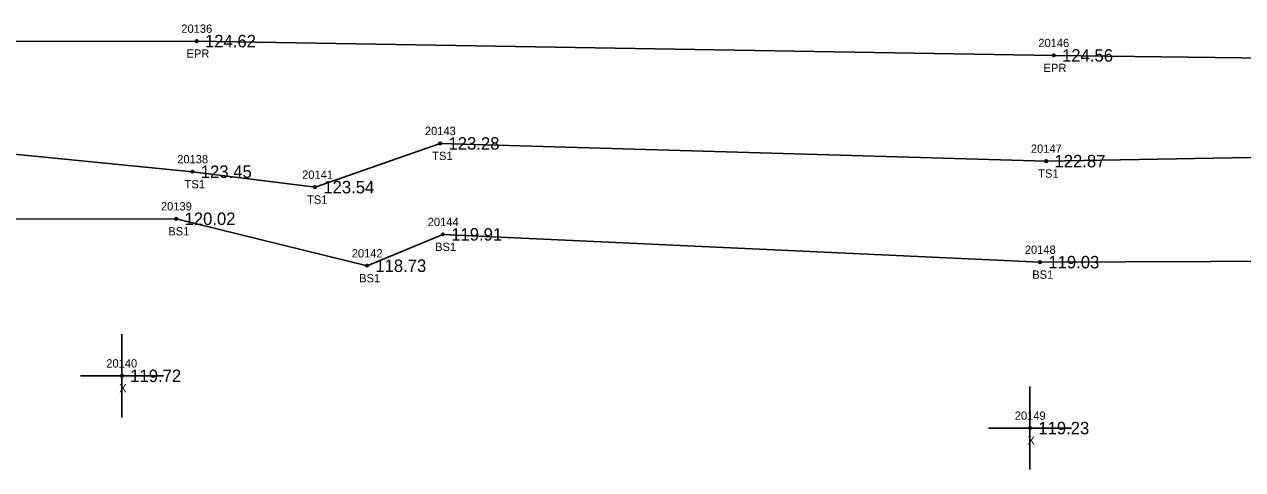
# Model space of a CAD drawing. Extents: x 2375812 to 2377225, y 1024470 to 1025135.
# Drawn here: x 2376638 to 2376784.6, y 1024863.9 to 1024917.5 of the extents above; entities that cross this region are included whole.
import ezdxf

# ---------------------------------------------------------------- set-up
doc = ezdxf.new("R2010")
doc.units = 0
for name, color, linetype in [('RD_DTM_BkLn2', 7, 'Continuous'), ('RD_DTM_BkLn_txCode', 7, 'Continuous'), ('RD_EX_Misc', 7, 'Continuous'), ('RD_EX_Misc_txCode', 7, 'Continuous'), ('RD_EX_Road', 7, 'Continuous'), ('RD_EX_Road_txCode', 7, 'Continuous'), ('RD_EX_TX_Misc_ELEV', 7, 'Continuous'), ('RD_EX_TX_Road_ELEV', 7, 'Continuous'), ('RD_SMD_Locator', 7, 'Continuous')]:
    doc.layers.add(name, color=color, linetype=linetype)

msp = doc.modelspace()

# ---------------------------------------------------------------- linework, layer by layer
at = {"layer": 'RD_DTM_BkLn2'}
for points in [[(2376561.53, 1024913.62), (2376561.38, 1024909.35), (2376658.21, 1024899.77), (2376672.96, 1024897.91), (2376688.03, 1024903.17), (2376760.99, 1024901.04), (2376828.16, 1024902.22), (2376853.81, 1024902.74), (2376860.1, 1024898.86), (2376865.34, 1024899.92), (2376875.73, 1024904.61), (2376896.78, 1024904.73), (2376899.24, 1024901.87), (2376965.55, 1024899.2), (2377063.48, 1024900.56), (2377114.6, 1024898.84), (2377167.13, 1024900.76), (2377217.62, 1024901.12)], [(2376543.21, 1024910.85), (2376558.6, 1024896.28), (2376588.49, 1024894.01), (2376656.25, 1024894.1), (2376679.22, 1024888.45), (2376688.36, 1024892.22), (2376760.25, 1024888.88), (2376862.95, 1024889.28), (2376867.73, 1024890.58), (2376879.38, 1024883.12), (2376893.75, 1024882.89), (2376900.24, 1024892.67), (2376965.04, 1024891.16), (2377064.46, 1024895.27), (2377115.01, 1024893.54), (2377167.33, 1024895.41), (2377217.32, 1024894.83)]]:
    msp.add_lwpolyline(points, dxfattribs=at)
at = {"layer": 'RD_EX_Misc'}
for p, q in [((2376649.71, 1024870.2), (2376649.71, 1024880.2)), ((2376644.71, 1024875.2), (2376654.71, 1024875.2)), ((2376759.04, 1024863.91), (2376759.04, 1024873.91)), ((2376754.04, 1024868.91), (2376764.04, 1024868.91))]:
    msp.add_line(p, q, dxfattribs=at)
at = {"layer": 'RD_EX_Road'}
msp.add_lwpolyline([(2376561.38, 1024915.36), (2376658.71, 1024915.48), (2376761.9, 1024913.76), (2376865.54, 1024912.46), (2376965.34, 1024911.98), (2377063.07, 1024911.1), (2377113.55, 1024910.69), (2377167.38, 1024909.96), (2377217.4, 1024910.82)], dxfattribs=at)
at = {"layer": 'RD_SMD_Locator'}
for centre in [(2376658.71, 1024915.48), (2376761.9, 1024913.76), (2376688.03, 1024903.17), (2376658.21, 1024899.77), (2376760.99, 1024901.04), (2376672.96, 1024897.91), (2376656.25, 1024894.1), (2376688.36, 1024892.22), (2376679.22, 1024888.45), (2376760.25, 1024888.88), (2376649.71, 1024875.2), (2376759.04, 1024868.91)]:
    msp.add_circle(centre, 0.15, dxfattribs=at)

# ---------------------------------------------------------------- texts
at = {"layer": 'RD_DTM_BkLn_txCode'}
for s, p in [('20143', (2376686.19, 1024904.17)), ('20147', (2376759.15, 1024902.04)), ('20138', (2376656.37, 1024900.77)), ('TS1', (2376687.07, 1024901.17)), ('20141', (2376671.41, 1024898.91)), ('TS1', (2376760.03, 1024899.04)), ('TS1', (2376657.25, 1024897.77)), ('TS1', (2376672, 1024895.91)), ('20139', (2376654.41, 1024895.1)), ('20144', (2376686.53, 1024893.22)), ('BS1', (2376655.3, 1024892.1)), ('BS1', (2376687.42, 1024890.22)), ('20142', (2376677.38, 1024889.45)), ('20148', (2376758.42, 1024889.88)), ('BS1', (2376678.27, 1024886.45)), ('BS1', (2376759.31, 1024886.88))]:
    msp.add_text(s, height=1, dxfattribs=at).set_placement(p)
at = {"layer": 'RD_EX_Misc_txCode'}
for s, p in [('20140', (2376647.83, 1024876.2)), ('X', (2376649.39, 1024873.2)), ('20149', (2376757.21, 1024869.91)), ('X', (2376758.73, 1024866.91))]:
    msp.add_text(s, height=1, dxfattribs=at).set_placement(p)
at = {"layer": 'RD_EX_Road_txCode'}
for s, p in [('20136', (2376656.86, 1024916.48)), ('20146', (2376760.04, 1024914.76)), ('EPR', (2376657.49, 1024913.48)), ('EPR', (2376760.67, 1024911.76))]:
    msp.add_text(s, height=1, dxfattribs=at).set_placement(p)
at = {"layer": 'RD_EX_TX_Misc_ELEV'}
for s, p in [('123.28', (2376689.03, 1024902.42)), ('122.87', (2376761.99, 1024900.29)), ('123.45', (2376659.21, 1024899.02)), ('123.54', (2376673.96, 1024897.16)), ('120.02', (2376657.25, 1024893.35)), ('119.91', (2376689.36, 1024891.47)), ('119.03', (2376761.25, 1024888.13)), ('118.73', (2376680.22, 1024887.7)), ('119.72', (2376650.71, 1024874.45)), ('119.23', (2376760.04, 1024868.16))]:
    msp.add_text(s, height=1.5, dxfattribs=at).set_placement(p)
at = {"layer": 'RD_EX_TX_Road_ELEV'}
for s, p in [('124.62', (2376659.71, 1024914.73)), ('124.56', (2376762.9, 1024913.01))]:
    msp.add_text(s, height=1.5, dxfattribs=at).set_placement(p)

doc.saveas('drawing.dxf')
